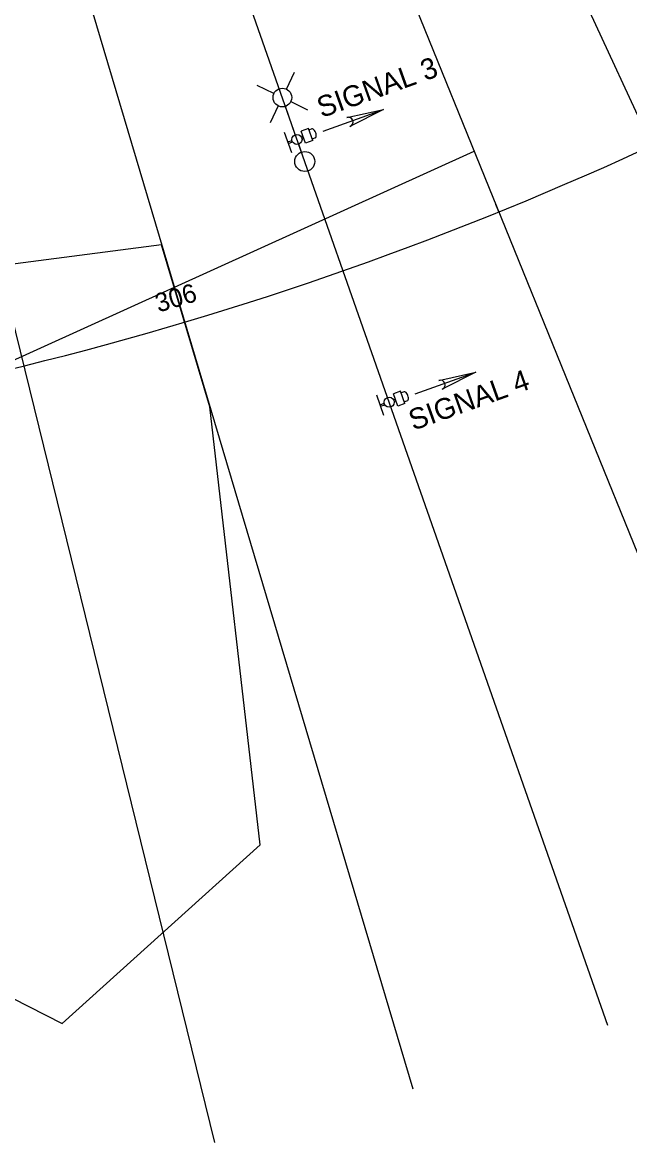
# Model space of a CAD drawing. Extents: x 153902 to 157473, y 413085 to 414252.
# Drawn here: x 154375.4 to 154466.5, y 413598.1 to 413766.1 of the extents above; entities that cross this region are included whole.
import ezdxf

# ---------------------------------------------------------------- set-up
doc = ezdxf.new("R2010")
doc.units = 0
for name, color, linetype in [('GE_P_Alignment', 7, 'Continuous'), ('PF_X_Ground_Line', 7, 'Continuous'), ('PV_X_Text', 7, 'Continuous'), ('SV_X_Text', 7, 'Continuous'), ('UT_X_Electric_Cells', 7, 'Continuous'), ('VG_X_Flower_Bed', 7, 'Continuous')]:
    doc.layers.add(name, color=color, linetype=linetype)

msp = doc.modelspace()

# ---------------------------------------------------------------- linework, layer by layer
at = {"layer": 'GE_P_Alignment'}
msp.add_arc((154251.74, 414218.49), 518.89, 280.6558, 303.1023, dxfattribs=at)
at = {"layer": 'PF_X_Ground_Line'}
for p, q in [((154446.9, 413737.7), (154446.45, 413738.81)), ((154399.73, 413721.15), (154399.16, 413723.07))]:
    msp.add_line(p, q, dxfattribs=at)
at = {"layer": 'PV_X_Text'}
for p, q in [((154520.26, 413638.77), (154419.39, 413856.54)), ((154401.76, 413848.89), (154492.03, 413626.51)), ((154463.24, 413615.62), (154383.79, 413842.09)), ((154365.51, 413836.17), (154433.96, 413606.14)), ((154404.26, 413598.07), (154346.96, 413831.13))]:
    msp.add_line(p, q, dxfattribs=at)
at = {"layer": 'SV_X_Text'}
msp.add_line((154370.63, 413713.92), (154443.19, 413746.82), dxfattribs=at)
at = {"layer": 'UT_X_Electric_Cells'}
msp.add_line((154411.04, 413642.76), (154381.35, 413615.96), dxfattribs=at)
msp.add_lwpolyline([(154202.4, 413670.72), (154326.58, 413643.87), (154381.35, 413615.96), (154411.04, 413642.76), (154403.51, 413708.45), (154396.28, 413732.77), (154358.14, 413727.79)], dxfattribs=at)
at = {"layer": 'VG_X_Flower_Bed'}
for p, q in [((154415, 413756.12), (154416.22, 413758.65)), ((154413.14, 413755.47), (154410.61, 413756.68)), ((154413.79, 413753.6), (154412.57, 413751.07)), ((154416.34, 413749.3), (154414.86, 413753.54)), ((154415.66, 413754.25), (154418.18, 413753.04)), ((154420.5, 413749.83), (154429.6, 413753.08)), ((154424.07, 413751.85), (154429.6, 413753.08)), ((154429.6, 413753.08), (154424.54, 413750.53)), ((154415.82, 413746.58), (154414.72, 413749.63)), ((154418.3, 413750.23), (154417.22, 413749.84)), ((154417.88, 413748.01), (154417.22, 413749.84)), ((154418.95, 413748.4), (154418.3, 413750.23)), ((154418.84, 413750.16), (154418.39, 413749.99)), ((154415.23, 413748.22), (154415.85, 413748.44)), ((154415.31, 413747.99), (154415.93, 413748.22)), ((154417.27, 413746.68), (154416.85, 413747.87)), ((154417.26, 413748.95), (154417.51, 413749.04)), ((154417.26, 413748.95), (154417.51, 413749.04)), ((154417.34, 413748.72), (154417.59, 413748.81)), ((154417.34, 413748.72), (154417.59, 413748.81)), ((154418.95, 413748.4), (154417.88, 413748.01)), ((154419.33, 413748.8), (154418.88, 413748.64)), ((154434.34, 413710.39), (154443.44, 413713.64)), ((154437.9, 413712.41), (154443.44, 413713.64)), ((154443.44, 413713.64), (154438.38, 413711.09)), ((154429.65, 413707.14), (154428.56, 413710.19)), ((154432.13, 413710.79), (154431.06, 413710.4)), ((154431.71, 413708.57), (154431.06, 413710.4)), ((154431.09, 413709.51), (154431.34, 413709.6)), ((154431.09, 413709.51), (154431.34, 413709.6)), ((154431.18, 413709.28), (154431.42, 413709.37)), ((154431.18, 413709.28), (154431.42, 413709.37)), ((154432.79, 413708.96), (154432.13, 413710.79)), ((154432.68, 413710.72), (154432.23, 413710.55)), ((154432.68, 413710.72), (154432.23, 413710.55)), ((154433.17, 413709.36), (154432.71, 413709.2)), ((154433.17, 413709.36), (154432.71, 413709.2)), ((154429.07, 413708.78), (154429.69, 413709)), ((154429.07, 413708.78), (154429.69, 413709)), ((154429.15, 413708.55), (154429.77, 413708.78)), ((154429.15, 413708.55), (154429.77, 413708.78)), ((154432.79, 413708.96), (154431.71, 413708.57))]:
    msp.add_line(p, q, dxfattribs=at)
for centre, radius in [((154414.4, 413754.86), 1.4), ((154416.59, 413748.58), 0.757), ((154417.76, 413745.27), 1.5), ((154430.43, 413709.14), 0.757)]:
    msp.add_circle(centre, radius, dxfattribs=at)
for centre, radius in [((154424.3, 413751.19), 0.703), ((154438.14, 413711.75), 0.702)]:
    msp.add_arc(centre, radius, 289.6702, 109.6702, dxfattribs=at)
for centre in [(154419.09, 413749.48), (154432.92, 413710.04), (154432.92, 413710.04)]:
    msp.add_ellipse(centre, major_axis=(0.244, -0.678), ratio=0.45371, start_param=0, end_param=3.141593, dxfattribs=at)

# ---------------------------------------------------------------- texts
at = {"layer": 'PF_X_Ground_Line'}
msp.add_text('306', height=2.8, rotation=16.5715, dxfattribs=at).set_placement((154395.8, 413722.59))
at = {"layer": 'VG_X_Flower_Bed'}
for s, p in [('SIGNAL 3', (154420.29, 413751.78)), ('SIGNAL 4', (154434.05, 413704.87))]:
    msp.add_text(s, height=3.125, rotation=19.6702, dxfattribs=at).set_placement(p)

doc.saveas('drawing.dxf')
